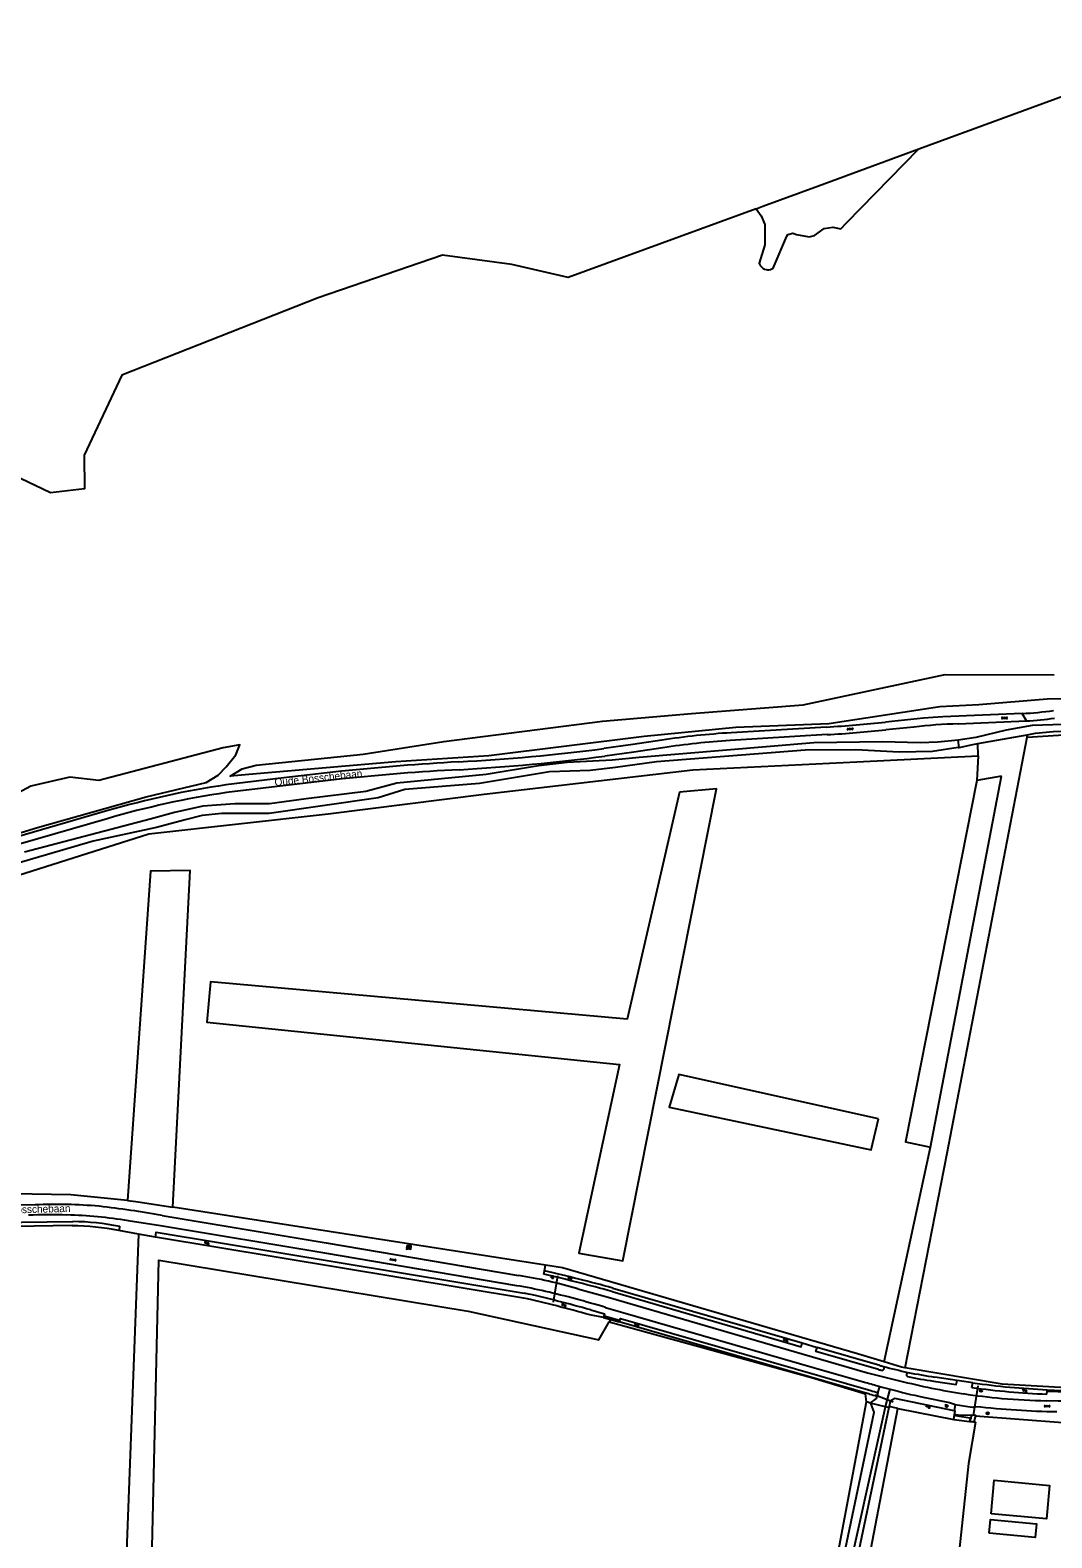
# Model space of a CAD drawing. Extents: x 137000 to 140001, y 403500 to 406000.
# Drawn here: x 137691 to 138031, y 405498 to 406000 of the extents above; entities that cross this region are included whole.
import ezdxf

# ---------------------------------------------------------------- set-up
doc = ezdxf.new("R2010")
doc.units = 0
for name, color, linetype in [('gg-afsc-draadraster', 7, 'Continuous'), ('gg-afsc-erfafscheiding', 7, 'Continuous'), ('gg-afsc-hekwerk', 7, 'Continuous'), ('gg-afsc-lijn draadraster', 7, 'Continuous'), ('gg-anno-openbare ruimte label', 7, 'Continuous'), ('gg-bbg-gedigitaliseerde bijgebouw', 7, 'Continuous'), ('gg-bbg-lage trafo', 7, 'Continuous'), ('gg-knt-bronhoudergrens', 7, 'Continuous'), ('gg-knt-onverhard', 7, 'Continuous'), ('gg-knt-verharding', 7, 'Continuous'), ('gg-knt-verharding nz', 7, 'Continuous'), ('gg-kntw-bovenkant insteek waterloop', 7, 'Continuous'), ('gg-kntw-greppel-droge sloot', 7, 'Continuous'), ('gg-kwrk-duiker nz buis', 7, 'Continuous'), ('gt-grn-groengrens', 7, 'Continuous'), ('gt-grn-vlakafsluiter', 7, 'Continuous'), ('gt-grn-weggrens', 7, 'Continuous'), ('gt-symb-boom', 7, 'Continuous'), ('gt-symb-gesloten verharding', 7, 'Continuous'), ('gt-symb-lichtmast', 7, 'Continuous'), ('gt-symb-trafo symbool', 7, 'Continuous'), ('gt-symb-watersymbool', 7, 'Continuous'), ('gx-grn-maaiveld', 7, 'Continuous')]:
    doc.layers.add(name, color=color, linetype=linetype)

# ---------------------------------------------------------------- blocks, each defined once
blk = doc.blocks.new('gt0-GESVH1')
at = {"layer": 'gt-symb-gesloten verharding'}
for p, q in [((-0.99, -0.26), (0.01, 0.24)), ((0.01, -0.26), (-0.99, 0.24)), ((0.01, 0.24), (1.01, -0.26)), ((1.01, 0.24), (0.01, -0.26))]:
    blk.add_line(p, q, dxfattribs=at)
blk = doc.blocks.new('gt0-BOOM')
at = {"layer": 'gt-symb-boom'}
for radius in [0.4, 0.2]:
    blk.add_circle((0, 0), radius, dxfattribs=at)
blk = doc.blocks.new('gt0-WA')
at = {"layer": 'gt-symb-watersymbool'}
for centre, start, end in [((-0.32, 0.02), 28.0725, 151.9275), ((0.43, 0.42), 208.0725, 331.9275), ((-0.32, -0.43), 28.0725, 151.9275), ((0.43, -0.03), 208.0725, 331.9275)]:
    blk.add_arc(centre, 0.425, start, end, dxfattribs=at)
blk = doc.blocks.new('gt0-LMAST')
at = {"layer": 'gt-symb-lichtmast'}
for p, q in [((-0.18, 0.17), (-0.45, 0.44)), ((-0.01, 0.25), (-0.01, 0.62)), ((0.17, 0.17), (0.44, 0.44)), ((-0.26, 0), (-0.63, 0)), ((-0.18, -0.18), (-0.45, -0.45)), ((-0.01, -0.25), (-0.01, -0.63)), ((0.44, -0.45), (0.17, -0.18)), ((0.24, 0), (0.62, 0))]:
    blk.add_line(p, q, dxfattribs=at)
blk.add_circle((-0.01, 0), 0.25, dxfattribs=at)
blk = doc.blocks.new('gt0-HSP')
at = {"layer": 'gt-symb-trafo symbool'}
for points in [[(0.77, 0.75), (-0.53, 0), (0.47, 0), (-0.83, -0.75)], [(-0.22, -0.24), (-0.83, -0.75), (-0.08, -0.48)]]:
    blk.add_lwpolyline(points, dxfattribs=at)

msp = doc.modelspace()

# ---------------------------------------------------------------- linework, layer by layer
at = {"layer": 'gg-afsc-draadraster'}
for p, q in [((137975.29, 405556.39), (137990.73, 405627.9)), ((137723.22, 405610.17), (137704.3, 405612)), ((137957.91, 405481.74), (137969.44, 405543.07)), ((137969.44, 405543.07), (137969.11, 405545.71)), ((137970.4, 405542.73), (137969.44, 405543.07))]:
    msp.add_line(p, q, dxfattribs=at)
for points in [[(138022.98, 405764.54), (138063.07, 405767.08), (138063.88, 405768.96)], [(137982.32, 405554.39), (137996.27, 405625.94), (138022.98, 405764.54)], [(137704.3, 405612), (137639.79, 405613.19), (137604.73, 405614.09)], [(138005.8, 405536.34), (138003.46, 405522.52), (137998.97, 405481.07), (137998.06, 405465.98)]]:
    msp.add_lwpolyline(points, dxfattribs=at)
at = {"layer": 'gg-afsc-erfafscheiding'}
for p, q in [((138005.72, 405538.47), (138034.88, 405536.15)), ((138005.18, 405536.41), (138005.8, 405536.34))]:
    msp.add_line(p, q, dxfattribs=at)
at = {"layer": 'gg-afsc-hekwerk'}
for p, q in [((137970.61, 405542.68), (137970.4, 405542.73)), ((137975.78, 405541.46), (137970.61, 405542.68)), ((137976.88, 405541.19), (137975.78, 405541.46))]:
    msp.add_line(p, q, dxfattribs=at)
at = {"layer": 'gg-afsc-lijn draadraster'}
for p, q in [((137957.91, 405481.74), (137969.44, 405543.07)), ((137969.44, 405543.07), (137969.11, 405545.71)), ((137998.49, 405537.17), (138004.65, 405536.47)), ((138005.18, 405536.41), (138005.8, 405536.34))]:
    msp.add_line(p, q, dxfattribs=at)
for points in [[(138022.98, 405764.54), (138063.07, 405767.08), (138063.88, 405768.96)], [(137982.32, 405554.39), (137996.27, 405625.94), (138022.98, 405764.54)], [(138005.8, 405536.34), (138003.46, 405522.52), (137998.97, 405481.07), (137998.06, 405465.98)]]:
    msp.add_lwpolyline(points, dxfattribs=at)
at = {"layer": 'gg-bbg-gedigitaliseerde bijgebouw'}
for points in [[(138010.94, 405505.83), (138012, 405516.97), (138030.45, 405515.22), (138029.39, 405504.08), (138010.94, 405505.83)], [(138010.28, 405499.32), (138010.71, 405503.9), (138026.09, 405502.44), (138025.65, 405497.86), (138010.28, 405499.32)]]:
    msp.add_lwpolyline(points, dxfattribs=at)
at = {"layer": 'gg-bbg-lage trafo'}
msp.add_lwpolyline([(137816.2, 405594.16), (137817.59, 405593.94), (137817.74, 405594.94), (137816.35, 405595.16), (137816.2, 405594.16)], dxfattribs=at)
at = {"layer": 'gg-knt-bronhoudergrens'}
for p, q in [((138006.68, 405758.22), (138006.18, 405750.03)), ((137990.73, 405627.9), (138014.38, 405751.48)), ((138014.38, 405751.48), (138006.18, 405750.03)), ((137862.44, 405588.6), (137738.28, 405607.94)), ((137726.92, 405598.97), (137720.36, 405600.14)), ((137726.92, 405598.97), (137722.78, 405490.19)), ((137884.12, 405570.52), (137883.65, 405569.7)), ((137884.12, 405570.52), (137887.06, 405569.7))]:
    msp.add_line(p, q, dxfattribs=at)
for points in [[(137598.1, 405689.92), (137601.31, 405690.94), (137649.42, 405706.11), (137677.71, 405715.62), (137730.32, 405732.28), (137790.09, 405738.92), (137842.06, 405745.47), (137911.56, 405753.61), (137966.2, 405756.33), (138006.68, 405758.22)], [(138006.18, 405750.03), (137982.42, 405629.7), (137990.73, 405627.9)], [(137907.12, 405746.12), (137889.72, 405670.51), (137750.84, 405682.97), (137749.7, 405669.52), (137887.13, 405655.41), (137873.59, 405592.64), (137888.21, 405590.11), (137919.48, 405747.25), (137907.12, 405746.12)], [(137738.28, 405607.94), (137744.16, 405720.05), (137730.9, 405719.83), (137723.22, 405610.17)], [(137973.43, 405637.34), (137906.9, 405652.17), (137903.66, 405641.21), (137970.95, 405627), (137973.43, 405637.34)], [(137731.38, 405489.93), (137733.72, 405590.3), (137836.68, 405573.27), (137880.21, 405563.75), (137883.65, 405569.7)], [(137975.29, 405556.39), (137966.46, 405559.12), (137868.13, 405587.72), (137862.44, 405588.6)], [(137883.65, 405569.7), (137951.12, 405551.18), (137969.11, 405545.71)], [(137982.32, 405554.39), (137981.13, 405554.59), (137975.29, 405556.39)], [(138035.98, 405547.72), (138014.62, 405548.96), (137982.32, 405554.39)]]:
    msp.add_lwpolyline(points, dxfattribs=at)
at = {"layer": 'gg-knt-onverhard'}
for p, q in [((138006.48, 405762.43), (138022.93, 405765.28)), ((138000, 405761.02), (138000.28, 405761.02)), ((137973.26, 405546.14), (137973.84, 405548.23)), ((137975.78, 405541.46), (137977.31, 405547.3))]:
    msp.add_line(p, q, dxfattribs=at)
for points in [[(138066.69, 405771.54), (138059.51, 405770.72), (138045.24, 405769.02), (138024.67, 405768.35), (138015.96, 405766.83), (138005.82, 405764.4), (138000, 405763.44)], [(138022.93, 405765.28), (138025.72, 405765.77), (138031.6, 405766.41), (138044.05, 405766.62), (138053.4, 405767.4), (138063.88, 405768.96)], [(138000.28, 405761.02), (138004.91, 405762.1), (138006.48, 405762.43)], [(137955.39, 405467.09), (137956.67, 405474.57), (137958.86, 405481.79), (137961.6, 405490), (137971.98, 405539.62), (137970.98, 405542.28), (137970.61, 405542.68)], [(137959.46, 405467.07), (137961.69, 405477.89), (137975.78, 405541.46)], [(137970.61, 405542.68), (137972.72, 405544.2), (137972.94, 405544.98)]]:
    msp.add_lwpolyline(points, dxfattribs=at)
at = {"layer": 'gg-knt-verharding'}
for p, q in [((137956.16, 405767.87), (137924.35, 405765.96)), ((137985.19, 405767.86), (137975.89, 405766.97)), ((138000, 405768.9), (138022.72, 405769.91)), ((137956.32, 405765.34), (137924.02, 405763.35)), ((137794.73, 405750.59), (137756.21, 405746.03))]:
    msp.add_line(p, q, dxfattribs=at)
for points in [[(138021.3, 405772.38), (137994.85, 405771.23), (137991.6, 405771.04), (137988.37, 405770.77), (137975.71, 405769.53)], [(137901.25, 405763.48), (137891.6, 405762), (137881.93, 405760.7)], [(137901.6, 405760.95), (137891.95, 405759.48), (137882.27, 405758.16)], [(137794.54, 405753.13), (137775.26, 405750.89), (137755.98, 405748.6)], [(137716.68, 405740.03), (137683.9, 405730.49), (137677.6, 405728.61), (137671.32, 405726.65), (137622.77, 405711.09)], [(137716.41, 405737.32), (137687.63, 405728.92), (137679.22, 405726.41), (137670.84, 405723.81), (137627.7, 405710.14), (137623.3, 405708.61)], [(137692.52, 405608.7), (137665.2, 405608.17), (137648.1, 405607.88), (137633.65, 405607.83)], [(137852.9, 405581.77), (137788.99, 405592.64), (137734.27, 405601.76), (137723.5, 405603.42)], [(137734.78, 405605.18), (137789.38, 405596.01), (137853.53, 405585.19)], [(137873.3, 405580.74), (137883.42, 405577.92), (137948.04, 405559.13), (137969.8, 405552.76)], [(137882.49, 405574.53), (137947.13, 405555.83), (137957.93, 405552.79), (137969.21, 405549.54)], [(137988.26, 405544.63), (137997.11, 405542.86), (137998.75, 405542.26), (137998.99, 405542.23)], [(137998.99, 405542.23), (138004.66, 405541.36), (138005.8, 405541.55)], [(138037.07, 405543.31), (138033.24, 405543.36), (138029.42, 405543.44)]]:
    msp.add_lwpolyline(points, dxfattribs=at)
for centre, radius, start, end in [((138016.74, 405875.91), 103.63, 272.5199, 278.3183), ((137935.42, 406128.21), 360.93, 273.2933, 276.4095), ((138002.63, 405624.99), 143.93, 91.0465, 96.9581), ((138018.36, 405860.82), 91.01, 272.7473, 278.6727), ((137939.23, 405518.67), 247.74, 93.4443, 98.82), ((137939.31, 405515.32), 248.51, 93.5267, 98.7278), ((137935.91, 406128.47), 363.7, 273.2168, 276.3095), ((137802.67, 406363.44), 607.92, 272.91222, 277.49222), ((137794.89, 406436.18), 683.62, 273.25343, 277.34319), ((137887.14, 404855.57), 902.32, 93.40461, 95.88998), ((137870.53, 405037.71), 716.89, 92.94539, 96.06905), ((137798.86, 405457.68), 294.06, 98.3849, 106.2267), ((137799.84, 405451.46), 297.79, 98.4258, 106.2709), ((137699.69, 405449.48), 159.38, 84.9108, 92.578), ((137667.8, 405219.36), 391.59, 80.1517, 83.2498), ((137697.61, 405213.99), 391.36, 89.209, 91.086), ((137699.3, 405454.11), 151.26, 80.7906, 88.5912), ((137822.12, 405400.52), 183.85, 77.3316, 80.3607), ((137825.78, 405415.64), 171.8, 73.9411, 80.7044), ((137786.97, 405257.55), 331.06, 73.2298, 76.8234), ((138071.49, 405932.53), 393.15, 255.0104, 258.2053), ((138055.22, 405844.88), 307.61, 253.762, 254.658), ((138050.87, 405828.14), 290.32, 254.6121, 255.322), ((138057.13, 405851.35), 314.36, 255.2899, 257.345), ((138035.14, 405765.27), 222, 258.5653, 261.3359), ((138035.01, 405764.9), 221.61, 261.3532, 264.6989), ((138045.6, 405924.97), 385.48, 264.0741, 266.0973), ((138038.23, 405847.62), 304.3, 265.5344, 268.3394), ((138034.87, 405767.17), 227.32, 266.0877, 269.498)]:
    msp.add_arc(centre, radius, start, end, dxfattribs=at)
at = {"layer": 'gg-knt-verharding nz'}
for points in [[(138000, 405763.44), (137993.15, 405762.84), (137987.28, 405762.64), (137974.8, 405762.98), (137951.87, 405762.64), (137893.67, 405757.77), (137884.72, 405756.81), (137869.66, 405756.07), (137860.21, 405754.96), (137842.74, 405752.1), (137812.97, 405749.2), (137802.63, 405746.36), (137782.72, 405743.92), (137770.56, 405742.28), (137759.01, 405742.32), (137748.33, 405741.53), (137738.9, 405739.39), (137730.76, 405737.14), (137688.92, 405726.23)], [(138000, 405761.02), (137991.37, 405759.69), (137980.28, 405759.55), (137965.9, 405760.29), (137948.97, 405760.18), (137899.48, 405756.22), (137885.77, 405754.41), (137877.36, 405753.36), (137863.83, 405752.93), (137840.47, 405749.11), (137815.63, 405747.02), (137806.78, 405744.24), (137770.42, 405739.01), (137754.62, 405739.09), (137748.1, 405738.45), (137742.48, 405737), (137732.88, 405734.4), (137711.79, 405729.8), (137671.47, 405718.13)]]:
    msp.add_lwpolyline(points, dxfattribs=at)
at = {"layer": 'gg-kntw-bovenkant insteek waterloop'}
for p, q in [((137704.75, 405601.77), (137637.72, 405600.85)), ((137637.77, 405602.22), (137705.03, 405603.14)), ((137720.64, 405601.51), (137720.36, 405600.14)), ((137855.11, 405577.67), (137732.53, 405597.97)), ((137861.94, 405585.62), (137862.13, 405586.75)), ((137884.92, 405580.97), (137948, 405562.73)), ((137881.78, 405571.16), (137877.27, 405572.05)), ((137970.46, 405545.68), (137887.06, 405569.7)), ((137973.87, 405555.22), (137953.02, 405561.14)), ((137999.6, 405550.16), (137992.18, 405551.33)), ((137973.26, 405546.14), (137972.94, 405544.98)), ((137976.95, 405541.48), (137976.88, 405541.19)), ((137965.98, 405468.38), (137979.9, 405540.89)), ((137979.9, 405540.89), (137998.49, 405537.17)), ((137998.49, 405537.17), (137998.78, 405538.86)), ((138004.5, 405538.53), (138004.58, 405538.8)), ((138005.72, 405538.47), (138005.18, 405536.41))]:
    msp.add_line(p, q, dxfattribs=at)
for points in [[(137732.53, 405597.97), (137732.81, 405599.62), (137855.39, 405579.32)], [(137884.73, 405579.84), (137947.63, 405561.42), (137948, 405562.73)], [(137877.55, 405573.7), (137882.13, 405572.39), (137881.78, 405571.16)], [(137887.06, 405569.7), (137887.45, 405570.84), (137970.84, 405546.82)], [(137973.43, 405553.88), (137952.58, 405559.8), (137953.02, 405561.14)], [(137991.74, 405549.99), (137999.32, 405548.91), (137999.6, 405550.16)], [(137998.66, 405540.06), (137978.85, 405544.17), (137977.37, 405543.26), (137976.95, 405541.48)], [(137976.88, 405541.19), (137963.16, 405476.2), (137960.83, 405466.25)], [(137998.78, 405538.86), (137998.98, 405539.99), (137998.66, 405540.06)], [(138004.65, 405536.47), (138003.91, 405536.68), (138004.5, 405538.53)], [(138004.58, 405538.8), (138005.77, 405538.65), (138005.72, 405538.47)], [(138005.18, 405536.41), (138005.16, 405536.33), (138004.65, 405536.47)]]:
    msp.add_lwpolyline(points, dxfattribs=at)
for centre, radius, start, end in [((137703.34, 405512.73), 89.05, 78.9791, 89.0896), ((137703.62, 405514.11), 89.05, 78.9791, 89.0896), ((137713.78, 404954.29), 649.63, 74.72541, 76.79897), ((137713.59, 404953.16), 649.63, 74.72541, 76.79897), ((137774.03, 405211.72), 374.82, 74.0129, 77.5086), ((137774.32, 405213.37), 374.82, 74.0129, 77.5086), ((138015.72, 405702.84), 154.85, 254.151, 254.5974), ((138020.42, 405719.39), 170.65, 254.1712, 254.5965), ((137974.55, 405554.32), 0.774, 272.9881, 45.6916), ((137983.48, 405552.17), 0.774, 107.3945, 238.5874), ((138011.34, 405687.5), 138.9, 258.2616, 261.8879), ((138011.68, 405688.21), 138.25, 258.1352, 261.8928), ((138038.58, 405781.82), 244.56, 253.9204, 254.5086), ((138041.73, 405792.89), 257.27, 253.9176, 254.4911)]:
    msp.add_arc(centre, radius, start, end, dxfattribs=at)
at = {"layer": 'gg-kntw-greppel-droge sloot'}
for p, q in [((138004.56, 405547.88), (138004.88, 405549.45)), ((138029.47, 405545.63), (138029.6, 405546.65)), ((138029.6, 405546.65), (138029.59, 405547.14))]:
    msp.add_line(p, q, dxfattribs=at)
for centre, radius, start, end in [((138039.28, 405793.16), 247.72, 261.9433, 267.7321), ((138040.11, 405792.5), 245.59, 261.7517, 267.5447)]:
    msp.add_arc(centre, radius, start, end, dxfattribs=at)
at = {"layer": 'gg-kwrk-duiker nz buis'}
for p, q in [((137865.16, 405576.3), (137866.62, 405585.06)), ((137887.48, 405570.1), (137881.69, 405571.78)), ((138005.11, 405538.52), (138006.65, 405548.43)), ((138029.6, 405546.65), (138036.62, 405546.45)), ((137978.27, 405542.96), (137972.36, 405545.33)), ((138004.58, 405537.57), (137998.37, 405538.53))]:
    msp.add_line(p, q, dxfattribs=at)
at = {"layer": 'gt-grn-groengrens'}
for p, q in [((138006.68, 405758.22), (138006.48, 405762.43)), ((138022.98, 405764.54), (138022.93, 405765.28)), ((137732.53, 405597.97), (137726.92, 405598.97)), ((137862.13, 405586.75), (137862.44, 405588.6)), ((137881.78, 405571.16), (137884.12, 405570.52)), ((137948, 405562.73), (137953.02, 405561.14)), ((138004.88, 405549.45), (137999.6, 405550.16)), ((138029.59, 405547.14), (138036.56, 405546.8)), ((137998.99, 405542.23), (137998.66, 405540.06))]:
    msp.add_line(p, q, dxfattribs=at)
for points in [[(137932.62, 405940.52), (137870.05, 405917.56), (137851.3, 405921.98), (137828.17, 405925.09), (137786.79, 405910.85), (137721.34, 405885.07), (137708.79, 405858.41), (137708.93, 405847.23), (137697.59, 405845.9), (137687.53, 405850.61), (137663.06, 405841.63)], [(138061.41, 405777.57), (138029.67, 405777.15), (138006.9, 405775.22), (137993.88, 405774.65), (137956.88, 405768.97), (137925.89, 405767.67), (137895.39, 405764.69), (137843.56, 405758.3), (137812.57, 405756.28), (137766.16, 405752.23), (137757.45, 405751.53), (137761.4, 405753.97), (137766.14, 405755.12), (137801.7, 405758.86), (137828.58, 405763.03), (137881.49, 405769.78), (137911.15, 405772.4), (137948.28, 405775.3), (137995.68, 405785.35), (138031.93, 405785.22)], [(137659.48, 405724.06), (137693.23, 405734.4), (137729.5, 405744.59), (137749.46, 405749.4), (137753.39, 405751.81), (137756.05, 405754.64), (137759.36, 405758.64), (137760.68, 405761.94), (137755.07, 405760.98), (137713.72, 405750.03), (137704.03, 405751.17), (137690.97, 405748.17), (137677.09, 405740.68)], [(137723.22, 405610.17), (137725.97, 405609.85), (137738.28, 405607.94)], [(138004.5, 405538.53), (138000, 405538.61), (137998.78, 405538.86)]]:
    msp.add_lwpolyline(points, dxfattribs=at)
msp.add_arc((138011.71, 405688.47), 138.52, 254.6719, 258.1433, dxfattribs=at)
at = {"layer": 'gt-grn-vlakafsluiter'}
for p, q in [((137979.9, 405540.89), (137976.95, 405541.48)), ((137998.49, 405537.17), (138004.65, 405536.47))]:
    msp.add_line(p, q, dxfattribs=at)
at = {"layer": 'gt-grn-weggrens'}
for p, q in [((138022.72, 405769.91), (138021.3, 405772.38)), ((138000.28, 405761.02), (138000, 405763.44))]:
    msp.add_line(p, q, dxfattribs=at)
at = {"layer": 'gx-grn-maaiveld'}
msp.add_line((137986.9, 405960.43), (138094.78, 406000), dxfattribs=at)
for points in [[(137932.62, 405940.52), (137934.33, 405938.11), (137935.61, 405935.25), (137935.56, 405928.53), (137933.71, 405922.34), (137933.79, 405922.09), (137934.01, 405921.65), (137934.29, 405921.25), (137934.64, 405920.9), (137935.04, 405920.61), (137935.48, 405920.39), (137935.95, 405920.24), (137936.43, 405920.17), (137936.93, 405920.18), (137937.41, 405920.27), (137937.87, 405920.44), (137938.3, 405920.68), (137942.88, 405931.4), (137943.23, 405931.9), (137944.93, 405932.35), (137946.13, 405931.94), (137950.37, 405931.19), (137952.06, 405931.55), (137955.28, 405933.91), (137958.24, 405934.38), (137960.93, 405933.87), (137962.81, 405935.77), (137986.9, 405960.43)], [(137932.62, 405940.52), (137934.9, 405941.35), (137953.41, 405948.14), (137986.9, 405960.43)]]:
    msp.add_lwpolyline(points, dxfattribs=at)

# ---------------------------------------------------------------- block references
at = {"layer": 'gt-symb-boom'}
for p in [(138007.62, 405546.84), (138009.81, 405539.26)]:
    msp.add_blockref('gt0-BOOM', p, dxfattribs=at)
at = {"layer": 'gt-symb-gesloten verharding'}
for p, rotation in [((137964, 405767.2), 6.030008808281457), ((137811.65, 405590.42), -10.01793447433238)]:
    msp.add_blockref('gt0-GESVH1', p, dxfattribs=dict(at, rotation=rotation))
for p in [(138015.43, 405770.86), (138029.62, 405541.67)]:
    msp.add_blockref('gt0-GESVH1', p, dxfattribs=at)
at = {"layer": 'gt-symb-lichtmast'}
for p in [(137864.81, 405584.61), (137996.11, 405541.74)]:
    msp.add_blockref('gt0-LMAST', p, dxfattribs=at)
at = {"layer": 'gt-symb-trafo symbool'}
msp.add_blockref('gt0-HSP', (137816.99, 405594.67), dxfattribs=at)
at = {"layer": 'gt-symb-watersymbool'}
for p, rotation in [((137749.59, 405596.02), -2.006538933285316), ((137870.6, 405584.15), -2.006538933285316), ((137868.57, 405575.3), -2.006538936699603), ((137892.88, 405568.59), -2.006538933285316), ((137942.47, 405563.65), -2.006538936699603), ((138022.12, 405546.81), 2.0065389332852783), ((137989.88, 405541.53), -2.006538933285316)]:
    msp.add_blockref('gt0-WA', p, dxfattribs=dict(at, rotation=rotation))

# ---------------------------------------------------------------- texts
at = {"layer": 'gg-anno-openbare ruimte label'}
for rotation, p in [(5.9, (137772.35, 405748.19)), (1.5, (137674.9, 405605.57))]:
    msp.add_text('Oude Bosschebaan', height=2.5, rotation=rotation, dxfattribs=at).set_placement(p)

doc.saveas('drawing.dxf')
